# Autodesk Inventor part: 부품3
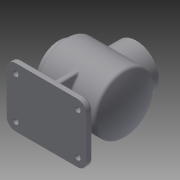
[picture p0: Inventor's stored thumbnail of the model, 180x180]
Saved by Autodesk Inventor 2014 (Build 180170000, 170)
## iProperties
Created: 2016-09
Part Number: 부품3
Material: Generic
Document SubType Name: Modeling
Designer: 702
Density: 1 g/cm^3
Appearance: Default
Author: 702
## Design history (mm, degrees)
sketch "스케치1"
  geometry: L1 (115, 0)-(5, 0); L2 (5, 0)-(5, 50); L3 (5, 50)-(103.562, 50); A1 r 115 centre (0, 0) between (115, 0) and (103.562, 50)
  constraints: 6 end point, 2 point on circle, 1 centre point, 1 horizontal, 1 parallel, 1 perpendicular
  dimensions: "d6" = 230 diameter of A1; "d7" = 110 distance of L1.start L1.end; "d8" = 50 distance of L1.end L2.end
revolve "회전1" sketch "스케치1" stored, may be unused: angle "d9" = 90 deg
sketch "스케치2"
  geometry: C1 r 50 at (0, 0) reference; C2 r 38 at (0, 0)
  constraints: 1 centre point, 1 coincident
  dimensions: "d10" = 76 diameter of C2
extrude "돌출1" join sketch "스케치2" distance "d11" = 12; taper "d12" = 0 deg
sketch "스케치3"
  geometry: C1 r 38 at (0, 0) reference; C2 r 27 at (0, 0)
  constraints: 1 centre point, 1 coincident
  dimensions: "d13" = 54 diameter of C2
extrude "돌출2" cut sketch "스케치3" distance "d14" = 15; taper "d15" = 0 deg
sketch "스케치5"
  geometry: L1 (5, -50)-(5, 50) reference; L2 (103.562, -50)-(103.562, 50) reference; L3 (103.562, -50)-(103.562, 50) reference; L4 (114.677, 0)-(111.677, 0); L5 (111.677, 0)-(8, 0); L6 (103.562, 50)-(103.562, 47); L7 (5, 50)-(8, 50); L8 (8, 50)-(8, 47); L9 (8, 47)-(101.634, 47); L10 (5, -50)-(8, -50); L11 (8, -50)-(8, -47); L12 (8, 0)-(8, 47); A1 r 115 centre (-3.323, 0) between (111.677, 0) and (101.634, 47); 1 further point
  constraints: 18 end point, 4 perpendicular, 2 parallel, 2 point on circle, 1 centre point, 1 collinear, 1 point on line
  dimensions: "d16" = 3 distance of L4.start L4.end; "d18" = 3 distance of L3.end L6.end; "d19" = 3 distance of L1.end L7.end; "d20" = 3 distance of L7.end L8.end; "d21" = 3 distance of L1.start L10.end; "d22" = 3 distance of L10.end L11.end
revolve "회전2" sketch "스케치5" stored, may be unused: angle "d23" = 90 deg
sketch "스케치6"
  geometry: 1 further point
node "작업 평면1"
sketch "스케치7"
  geometry: L1 (-5, 50)-(-5, -50) reference; L2 (-103.562, 50)-(-103.562, -50) reference; L3 (-8.857, 0)-(-58.857, 0); C1 r 38 at (-58.857, 0); 1 further point
  constraints: 2 end point, 1 centre point, 1 coincident, 1 perpendicular
  dimensions: "d25" = 50 distance of L3.start L3.end; "d26" = 76 diameter of C1
extrude "돌출3" join sketch "스케치7" stored distance "d27" = 15; taper "d28" = 0 deg
sketch "스케치8"
  geometry: C1 r 38 at (0, 0) reference; C2 r 27 at (0, 0); 1 further point
  constraints: 1 centre point, 1 coincident
  dimensions: "d29" = 54 diameter of C2
extrude "돌출4" cut sketch "스케치8" distance "d30" = 50; taper "d31" = 0 deg
sketch "스케치9"
  geometry: 1 further point
node "작업 평면2"
sketch "스케치10"
  geometry: L1 (-103.562, 50)-(-103.562, -50) reference; L2 (-5, 50)-(-5, -50) reference; 2 further points
  constraints: 1 other
  node "투영된 루프4"
sketch "스케치11"
  geometry: L1 (-5, 50)-(-5, -50) reference; L2 (-60, 0)-(-60, 50); L3 (-115, 0)-(-60, 0); L4 (-60, 50)-(-127.5, 50); L5 (-127.5, 50)-(-127.5, -50); L6 (-127.5, -50)-(7.5, -50); L7 (7.5, -50)-(7.5, 50); L8 (7.5, 50)-(-60, 50); A1 r 115 centre (3.323, 0) between (-101.634, 47) and (-101.634, -47) reference; A2 r 115 centre (0, 0) between (-103.562, 50) and (-103.562, -50) reference; 1 further point
  constraints: 14 end point, 3 perpendicular, 2 parallel, 1 point on circle
  dimensions: "d34" = 50 distance of L2.start L2.end; "d36" = 55 distance of L3.start L2.start; "d37" = 67.5 distance of L2.end L4.end; "d38" = 100 distance of L4.end L5.end; "d39" = 135 distance of L5.end L6.end; "d40" = 100 distance of L6.end L7.end
sketch "스케치12"
  geometry: L1 (-103.562, 50)-(-103.562, -50) reference; L2 (-5, 50)-(-5, -50) reference; L3 (7, -38)-(7, 38) reference; L4 (7, 0)-(-54, 0); L5 (-54, 0)-(-54, 50); L6 (-54, 50)-(13.5, 50); L7 (13.5, 50)-(13.5, -50); L8 (13.5, -50)-(-121.5, -50); L9 (-121.5, -50)-(-121.5, 50); L10 (-121.5, 50)-(-54, 50); A1 r 115 centre (0, 0) between (-103.562, 50) and (-103.562, -50) reference; 2 further points
  constraints: 14 end point, 4 parallel, 2 perpendicular, 1 midpoint, 1 other
  dimensions: "d43" = 61 distance of L4.start L4.end; "d44" = 50 distance of L4.end L5.end; "d45" = 67.5 distance of L5.end L6.end; "d46" = 100 distance of L6.end L7.end; "d47" = 135 distance of L7.end L8.end; "d48" = 100 distance of L8.end L9.end
extrude "돌출5" join sketch "스케치12" distance "d49" = 10; taper "d50" = 0 deg
fillet "모깎기1" dims "d69" = 15
sketch "스케치17"
  geometry: L1 (14, -5)-(14, 5) reference; L2 (14, 5)-(94, 5) reference; L3 (54, -5)-(14, -5) reference; L4 (94, -5)-(54, -5) reference; L5 (94, 5)-(94, -5) reference; L6 (14, 5)-(94, 5); L7 (94, -5)-(14, -5); L8 (54, 45)-(49, 45); L9 (54, 0)-(54, 40); L10 (54, 40)-(49, 40); L11 (49, 40)-(49, -40); L12 (49, -40)-(59, -40); L13 (59, -40)-(59, 40); L14 (59, 40)-(49, 40); 1 further point
  constraints: 18 end point, 5 perpendicular, 1 collinear, 1 parallel
  dimensions: "d73" = 5 distance of L8.start L8.end; "d75" = 40 distance of L9.start L9.end; "d76" = 5 distance of L9.end L10.end; "d77" = 80 distance of L10.end L11.end; "d78" = 10 distance of L11.end L12.end; "d79" = 80 distance of L12.end L13.end
extrude "돌출9" join sketch "스케치17" stored distance "d80" = 10; taper "d81" = 0 deg
sketch "스케치18"
  geometry: L1 (0, 22.251)-(35, 22.251) reference; L2 (0, 0)-(0, 22.251) reference; L3 (35, 0)-(0, 0) reference; L4 (35, 0)-(35, 22.251) reference; 1 further point
fillet "모깎기4" dims "d82" = 3
sketch "스케치19"
  geometry: C1 r 5 at (1.5, 35); C2 r 5 at (1.5, -35); C3 r 5 at (106.5, -35); C4 r 5 at (106.5, 35); A1 r 15 centre (106.5, 35) between (121.5, 35) and (106.5, 50) reference; A2 r 15 centre (1.5, 35) between (1.5, 50) and (-13.5, 35) reference; A3 r 15 centre (1.5, -35) between (-13.5, -35) and (1.5, -50) reference; A4 r 15 centre (106.5, -35) between (106.5, -50) and (121.5, -35) reference; 1 further point
  constraints: 4 centre point, 4 coincident
  dimensions: "d84" = 10 diameter of C1; "d85" = 10 diameter of C2; "d86" = 10 diameter of C3; "d87" = 10 diameter of C4
extrude "돌출10" cut sketch "스케치19" distance "d88" = 100; taper "d89" = 0 deg
sketch "스케치20"
  geometry: C1 r 38 at (0, 0) reference; A1 r 32.5 centre (0, 0) between (0, 32.5) and (-32.5, 0); 2 further points
  constraints: 4 point on circle, 1 centre point, 1 coincident
  dimensions: "d90" = 65 diameter of A1
hole "구멍1" sketch "스케치20" at (32.5, 0), (0, 32.5), (-32.5, 0), (0, -32.5) diameter "d91" = 3.242; stored, may be unused: countersink angle "d95" = 90 deg, drill point angle "d97" = 118 deg; dims "d92" = 8, "d93" = 4, "d94" = 2, "d96" = 10
sketch "스케치21"
  geometry: C1 r 27 at (0, 0) reference; A1 r 32.5 centre (0, 0) between (32.5, 0) and (0, 32.5); 3 further points
  constraints: 4 point on circle, 1 centre point, 1 coincident
  dimensions: "d98" = 65 diameter of A1
hole "구멍2" sketch "스케치21" at (32.5, 0), (0, 32.5), (0, -32.5), (-32.5, 0) diameter "d99" = 3.242; stored, may be unused: countersink angle "d103" = 90 deg, drill point angle "d105" = 118 deg; dims "d100" = 8, "d101" = 4, "d102" = 2, "d104" = 10
chamfer "모따기1" distance "d106" = 1; stored, may be unused: second distance "d107" = 2, angle "d108" = 45 deg
fillet "모깎기5" dims "d109" = 5
fillet "모깎기6" dims "d110" = 3
fillet "모깎기7" dims "d111" = 2
fillet "모깎기8" dims "d112" = 3
node "솔리드1"
node "투영된 루프1"
node "투영된 루프2"
node "투영된 루프3"
node "투영된 루프5"
other parameters: "d24" = 65, "d32" = -82
